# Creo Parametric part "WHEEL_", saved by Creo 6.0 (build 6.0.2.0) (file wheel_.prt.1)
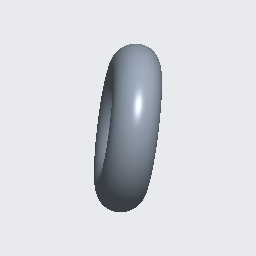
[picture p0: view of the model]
Units: Inch lbm Second (Pro/E Default); INCH, POUND, SECS

Created from: INLBS_PART_SOLID.PRT

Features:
  1. datum plane "RIGHT"
  2. datum plane "TOP"
  3. datum plane "FRONT"
  4. coordinate system
  5. sketch "Sketch 1"
  6. revolve "Revolve 1"
  7. sketch "Sketch 2"
  8. extruded cut "Extrude 1"
  9. sketch "Sketch 3"
  10. pattern "Pattern 1"
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
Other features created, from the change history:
  extruded cut "Extrude 2"
  extruded cut "Extrude 2 [2]"
  extruded cut "Extrude 2 [3]"
  extruded cut "Extrude 2 [4]"
  extruded cut "Extrude 2 [5]"

Surfaces: 10 cone, 6 cylinder, 2 plane, 2 torus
